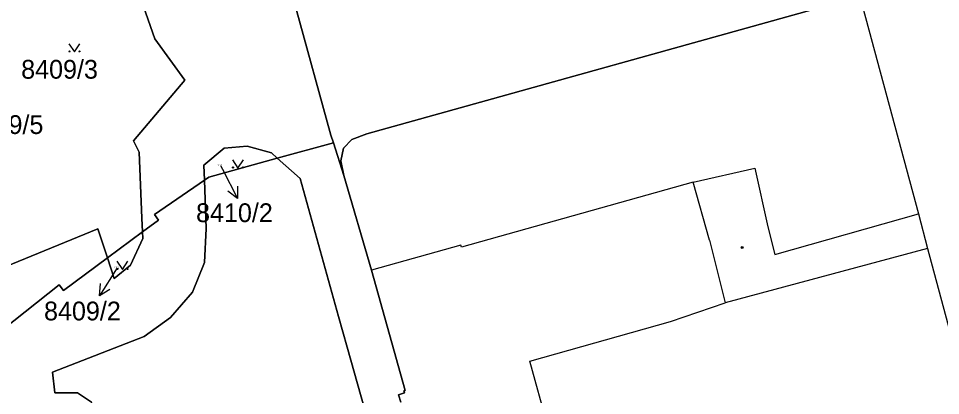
# Model space of a CAD drawing. Extents: x -596233 to -595156, y -1161235 to -1159375.
# Drawn here: x -595530.5 to -595447, y -1160239.5 to -1160205.3 of the extents above; entities that cross this region are included whole.
import ezdxf

# ---------------------------------------------------------------- set-up
doc = ezdxf.new("R2010")
doc.units = 0
for name, color, linetype in [('KN_CAR_KR', 7, 'Continuous'), ('KN_KULTURY', 7, 'Continuous'), ('KN_PARC_CIS_POM', 7, 'Continuous'), ('KN_PARC_CIS_POZ', 7, 'Continuous'), ('KN_PARC_PLOCHA', 7, 'Continuous'), ('PARC_C_SIPKA', 7, 'Continuous'), ('parcely_l', 7, 'Continuous')]:
    doc.layers.add(name, color=color, linetype=linetype)

msp = doc.modelspace()

# ---------------------------------------------------------------- linework, layer by layer
at = {"layer": 'KN_CAR_KR'}
for points in [[(-595454.32, -1160203.3), (-595449.01, -1160223.02)], [(-595469.41, -1160220.14), (-595463.81, -1160218.89)], [(-595463.81, -1160218.89), (-595462.63, -1160224.2)], [(-595469.41, -1160220.14), (-595490.38, -1160226.05)], [(-595467.94, -1160225.39), (-595469.41, -1160220.14)], [(-595462, -1160226.7), (-595449.01, -1160223.02)], [(-595449.01, -1160223.02), (-595448.17, -1160226.15)], [(-595462.63, -1160224.2), (-595462, -1160226.7)], [(-595490.44, -1160225.85), (-595498.55, -1160228.13)], [(-595490.38, -1160226.05), (-595490.44, -1160225.85)], [(-595467.94, -1160225.39), (-595466.5, -1160231.07)], [(-595448.17, -1160226.15), (-595466.5, -1160231.07)], [(-595448.17, -1160226.15), (-595445.51, -1160236.03)], [(-595471.45, -1160232.76), (-595466.5, -1160231.07)], [(-595484.2, -1160236.36), (-595471.45, -1160232.76)], [(-595482.6, -1160242.16), (-595484.2, -1160236.36)]]:
    msp.add_lwpolyline(points, dxfattribs=at)
at = {"layer": 'KN_KULTURY'}
for points in [[(-595525.9518, -1160207.6116), (-595525.4518, -1160208.3616), (-595524.9518, -1160207.6116)], [(-595511.1418, -1160218.1216), (-595510.6418, -1160218.8716), (-595510.1418, -1160218.1216)], [(-595521.6018, -1160227.3116), (-595521.1018, -1160228.0616), (-595520.6018, -1160227.3116)]]:
    msp.add_lwpolyline(points, dxfattribs=at)
for centre, radius in [((-595525.902, -1160208.3114), 0.05), ((-595525.0026, -1160208.3114), 0.05), ((-595511.092, -1160218.8214), 0.05), ((-595510.1926, -1160218.8214), 0.05), ((-595464.97, -1160226.06), 0.09), ((-595464.97, -1160226.06), 0.0398), ((-595521.552, -1160228.0114), 0.05), ((-595520.6526, -1160228.0114), 0.05)]:
    msp.add_circle(centre, radius, dxfattribs=at)
at = {"layer": 'KN_PARC_PLOCHA'}
for points in [[(-595531.59, -1160176.39), (-595528.97, -1160183.55), (-595528.21, -1160186.55), (-595524.38, -1160198.02), (-595520.02, -1160201.88), (-595518.18, -1160207.18), (-595515.46, -1160210.9), (-595520.1, -1160216.4), (-595519.58, -1160217.44), (-595519.36, -1160223.41), (-595519.29, -1160224.66), (-595522.46, -1160227.02), (-595523.32, -1160224.39), (-595531.74, -1160227.82)], [(-595442.07, -1160199.91), (-595454.32, -1160203.3), (-595498.98, -1160215.76), (-595500.32, -1160216.3), (-595501.08, -1160217.07), (-595501.33, -1160218.22), (-595501.05, -1160219.55), (-595502, -1160216.58), (-595502.22, -1160215.9), (-595505.41, -1160204.35), (-595491.91, -1160200.63), (-595485.08, -1160198.75), (-595478.31, -1160196.89), (-595471.56, -1160195.04), (-595465.78, -1160193.48), (-595460.21, -1160191.98), (-595454.87, -1160190.47), (-595449.14, -1160188.86), (-595437.97, -1160185.71)], [(-595495.88, -1160240.08), (-595496.09, -1160239.41), (-595495.55, -1160239.24), (-595495.6, -1160239.05), (-595495.5, -1160239.02), (-595498.55, -1160228.13), (-595501.05, -1160219.55), (-595501.33, -1160218.22), (-595501.08, -1160217.07), (-595500.32, -1160216.3), (-595498.98, -1160215.76), (-595454.32, -1160203.3), (-595442.07, -1160199.91), (-595439.38, -1160209.91), (-595436.61, -1160209.16), (-595433.04, -1160222.09), (-595435.85, -1160222.85), (-595433.03, -1160232.53), (-595430.29, -1160231.74), (-595425.26, -1160249.8)], [(-595505.41, -1160204.35), (-595502.22, -1160215.9), (-595502, -1160216.58), (-595507.08, -1160217.97), (-595507.59, -1160217.51), (-595509.82, -1160216.9), (-595511.88, -1160217.06), (-595513.73, -1160218.62), (-595513.68, -1160219.98), (-595518.21, -1160223.07), (-595517.83, -1160223.58), (-595519.29, -1160224.66), (-595519.36, -1160223.41), (-595519.58, -1160217.44), (-595520.1, -1160216.4), (-595515.46, -1160210.9), (-595518.18, -1160207.18), (-595520.02, -1160201.88)], [(-595557.56, -1160251.17), (-595561.88, -1160238.61), (-595562.54, -1160236.89), (-595557.62, -1160233.21), (-595553.32, -1160229.8), (-595549.91, -1160226.51), (-595542.62, -1160219.37), (-595540.4, -1160217.19), (-595538.53, -1160215.05), (-595537.83, -1160216.82), (-595534.92, -1160224.16), (-595533.12, -1160228.38), (-595531.74, -1160227.82), (-595523.32, -1160224.39), (-595522.46, -1160227.02), (-595526.43, -1160229.97), (-595526.85, -1160229.46), (-595536.26, -1160236.91), (-595544.03, -1160243.06)], [(-595490, -1160273.23), (-595500.75, -1160235.11), (-595501.53, -1160232.33), (-595505.01, -1160219.82), (-595507.08, -1160217.97), (-595502, -1160216.58), (-595501.05, -1160219.55), (-595498.55, -1160228.13), (-595495.5, -1160239.02), (-595495.6, -1160239.05), (-595495.55, -1160239.24), (-595496.09, -1160239.41), (-595495.88, -1160240.08)], [(-595523.91, -1160240.08), (-595525.17, -1160239.22), (-595527.23, -1160239.22), (-595527.44, -1160237.35), (-595519.15, -1160234.12), (-595516.75, -1160232.42), (-595514.77, -1160230.11), (-595513.68, -1160227.42), (-595513.51, -1160224.35), (-595513.68, -1160219.98), (-595513.27, -1160219.7), (-595507.08, -1160217.97), (-595505.01, -1160219.82), (-595501.53, -1160232.33), (-595500.75, -1160235.11), (-595490, -1160273.23)], [(-595532.71, -1160245.83), (-595536.26, -1160236.91), (-595526.85, -1160229.46), (-595526.43, -1160229.97), (-595522.46, -1160227.02), (-595521.85, -1160228.88), (-595520.38, -1160227.66), (-595519.25, -1160225.26), (-595519.29, -1160224.66), (-595517.83, -1160223.58), (-595518.21, -1160223.07), (-595513.68, -1160219.98), (-595513.51, -1160224.35), (-595513.68, -1160227.42), (-595514.77, -1160230.11), (-595516.75, -1160232.42), (-595519.15, -1160234.12), (-595527.44, -1160237.35), (-595527.23, -1160239.22), (-595525.17, -1160239.22), (-595523.91, -1160240.08)]]:
    msp.add_lwpolyline(points, dxfattribs=at)
for points in [[(-595507.08, -1160217.97), (-595513.27, -1160219.7), (-595513.68, -1160219.98), (-595513.73, -1160218.62), (-595511.88, -1160217.06), (-595509.82, -1160216.9), (-595507.59, -1160217.51)], [(-595522.46, -1160227.02), (-595519.29, -1160224.66), (-595519.25, -1160225.26), (-595520.38, -1160227.66), (-595521.85, -1160228.88)]]:
    msp.add_lwpolyline(points, close=True, dxfattribs=at)
at = {"layer": 'PARC_C_SIPKA'}
for points in [[(-595512.21, -1160218.64), (-595512.04, -1160218.96), (-595510.6663, -1160221.627)], [(-595510.6797, -1160220.5091), (-595510.6663, -1160221.627), (-595511.5687, -1160220.967)], [(-595521.57, -1160227.9), (-595521.58, -1160227.91), (-595523.1932, -1160230.4393)], [(-595522.2339, -1160229.8651), (-595523.1932, -1160230.4393), (-595523.077, -1160229.3274)]]:
    msp.add_lwpolyline(points, dxfattribs=at)
at = {"layer": 'parcely_l'}
for points in [[(-595575.35, -1160120.3), (-595583.07, -1160099.91), (-595582.73, -1160099.87), (-595565.76, -1160124.85), (-595564.1, -1160127.27), (-595549.64, -1160148.55), (-595547.86, -1160151.1), (-595535.02, -1160170.05), (-595531.59, -1160176.39), (-595528.97, -1160183.55), (-595528.21, -1160186.55), (-595524.38, -1160198.02), (-595520.02, -1160201.88), (-595518.18, -1160207.18), (-595515.46, -1160210.9), (-595520.1, -1160216.4), (-595519.58, -1160217.44), (-595519.36, -1160223.41), (-595519.29, -1160224.66)], [(-595501.05, -1160219.55), (-595501.33, -1160218.22), (-595501.08, -1160217.07), (-595500.32, -1160216.3), (-595498.98, -1160215.76), (-595454.32, -1160203.3), (-595442.07, -1160199.91)], [(-595505.41, -1160204.35), (-595502.22, -1160215.9), (-595502, -1160216.58)], [(-595522.46, -1160227.02), (-595523.32, -1160224.39), (-595531.74, -1160227.82), (-595533.12, -1160228.38), (-595534.92, -1160224.16), (-595537.83, -1160216.82), (-595538.53, -1160215.05)], [(-595502, -1160216.58), (-595507.08, -1160217.97)], [(-595501.05, -1160219.55), (-595502, -1160216.58)], [(-595507.08, -1160217.97), (-595507.59, -1160217.51), (-595509.82, -1160216.9), (-595511.88, -1160217.06), (-595513.73, -1160218.62), (-595513.68, -1160219.98)], [(-595513.68, -1160219.98), (-595513.27, -1160219.7), (-595507.08, -1160217.97)], [(-595507.08, -1160217.97), (-595505.01, -1160219.82), (-595501.53, -1160232.33), (-595500.75, -1160235.11), (-595490, -1160273.23), (-595488.33, -1160279.24), (-595485.8, -1160288.35), (-595485.92, -1160289.72), (-595486.87, -1160290.74), (-595492.67, -1160292.36)], [(-595507.42, -1160283.58), (-595507.48, -1160283.34), (-595508.77, -1160278.73), (-595523.91, -1160240.08), (-595525.17, -1160239.22), (-595527.23, -1160239.22), (-595527.44, -1160237.35), (-595519.15, -1160234.12), (-595516.75, -1160232.42), (-595514.77, -1160230.11), (-595513.68, -1160227.42), (-595513.51, -1160224.35), (-595513.68, -1160219.98)], [(-595519.29, -1160224.66), (-595517.83, -1160223.58), (-595518.21, -1160223.07), (-595513.68, -1160219.98)], [(-595495.88, -1160240.08), (-595496.09, -1160239.41), (-595495.55, -1160239.24), (-595495.6, -1160239.05), (-595495.5, -1160239.02), (-595498.55, -1160228.13), (-595501.05, -1160219.55)], [(-595522.46, -1160227.02), (-595519.29, -1160224.66)], [(-595519.29, -1160224.66), (-595519.25, -1160225.26), (-595520.38, -1160227.66), (-595521.85, -1160228.88), (-595522.46, -1160227.02)], [(-595536.26, -1160236.91), (-595526.85, -1160229.46), (-595526.43, -1160229.97), (-595522.46, -1160227.02)]]:
    msp.add_lwpolyline(points, dxfattribs=at)

# ---------------------------------------------------------------- texts
at = {"layer": 'KN_PARC_CIS_POM'}
for s, p in [('8410/2', (-595512.4933, -1160218.64)), ('8409/2', (-595521.8533, -1160227.9))]:
    msp.add_text(s, height=0.1, dxfattribs=at).set_placement(p)
at = {"layer": 'KN_PARC_CIS_POZ'}
for s, p in [('8409/3', (-595530.2766, -1160210.78)), ('8409/5', (-595535.2166, -1160215.79)), ('8410/2', (-595514.4366, -1160223.77)), ('8409/2', (-595528.2066, -1160232.67))]:
    msp.add_text(s, height=1.7, dxfattribs=at).set_placement(p)

doc.saveas('drawing.dxf')
